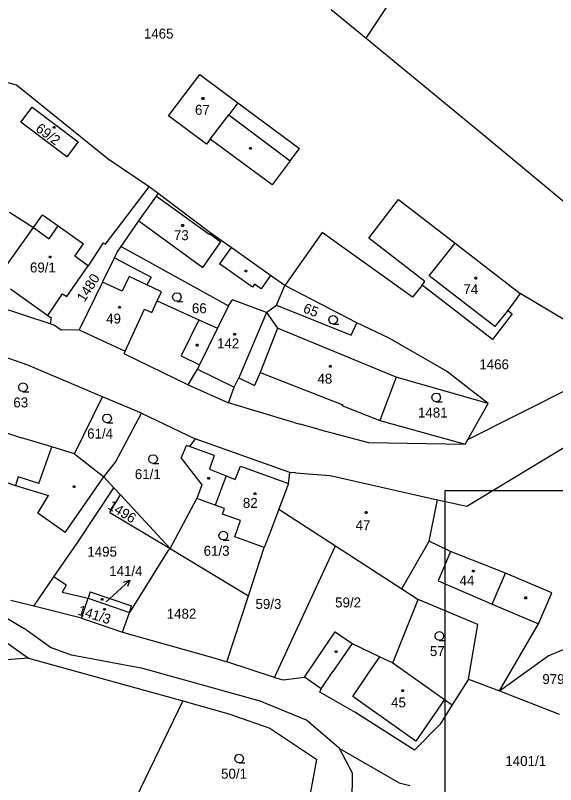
# Model space of a CAD drawing. Extents: x -852001 to -842497, y -1063614 to -1052182.
# Drawn here: x -849216.3 to -849124, y -1056255.4 to -1056124 of the extents above; entities that cross this region are included whole.
import ezdxf

# ---------------------------------------------------------------- set-up
doc = ezdxf.new("R2010")
doc.units = 0
for name, color, linetype in [('Default', 7, 'Continuous'), ('KN_HRANICE', 7, 'Continuous'), ('KN_KULTURY', 7, 'Continuous'), ('KN_PARCELY', 7, 'Continuous'), ('KN_SLUCKY', 7, 'Continuous'), ('LEGENDA', 7, 'Continuous')]:
    doc.layers.add(name, color=color, linetype=linetype)

# ---------------------------------------------------------------- blocks, each defined once
blk = doc.blocks.new('304')
at = {"layer": 'Default'}
blk.add_lwpolyline([(0, 0), (-0.38, 0.1), (-0.65, 0.37), (-0.75, 0.74), (-0.65, 1.11), (-0.38, 1.38), (-0.01, 1.48), (0.36, 1.38), (0.63, 1.11), (0.73, 0.73), (0.63, 0.35), (0.36, 0.08), (-0.02, -0.02), (0.98, -0.02)], dxfattribs=at)
blk = doc.blocks.new('NAHRADNI_SYMBOL')
at = {"layer": 'Default'}
blk.add_lwpolyline([(0.09, 0.15), (0.18, 0), (0.09, -0.15), (-0.09, -0.15), (-0.18, 0), (-0.09, 0.15), (0.09, 0.15)], dxfattribs=at)
blk = doc.blocks.new('10292')
at = {"layer": 'Default'}
blk.add_line((0, 3), (0, 0), dxfattribs=at)
blk.add_lwpolyline([(-0.5, 2), (0, 3), (0.5, 2)], dxfattribs=at)
blk = doc.blocks.new('402')
at = {"layer": 'Default'}
blk.add_lwpolyline([(0.09, 0.15), (0.18, 0), (0.09, -0.15), (-0.09, -0.15), (-0.18, 0), (-0.09, 0.15), (0.09, 0.15)], dxfattribs=at)

msp = doc.modelspace()

# ---------------------------------------------------------------- linework, layer by layer
at = {"layer": 'KN_HRANICE'}
for p, q in [((-849156.39, -1056127.95), (-849134.65, -1056094.95)), ((-849162.35, -1056123.05), (-849156.39, -1056127.95)), ((-849156.39, -1056127.95), (-849136.05, -1056144.68)), ((-849216.14, -1056135.95), (-849229.16, -1056132.38)), ((-849190.13, -1056141.21), (-849184.82, -1056134.14)), ((-849184.82, -1056134.14), (-849178.32, -1056138.97)), ((-849200.44, -1056148.6), (-849216.14, -1056135.95)), ((-849178.32, -1056138.97), (-849167.78, -1056146.8)), ((-849183.69, -1056146.04), (-849190.13, -1056141.21)), ((-849136.05, -1056144.68), (-849108.72, -1056167.41)), ((-849183.02, -1056145.16), (-849183.69, -1056146.04)), ((-849172.44, -1056152.99), (-849183.02, -1056145.16)), ((-849169.35, -1056148.89), (-849167.78, -1056146.8)), ((-849193.48, -1056153.3), (-849200.44, -1056148.6)), ((-849169.35, -1056148.89), (-849172.44, -1056152.99)), ((-849200.94, -1056163.12), (-849193.48, -1056153.3)), ((-849191.92, -1056154.48), (-849193.48, -1056153.3)), ((-849195.24, -1056159.11), (-849192.23, -1056154.91)), ((-849192.23, -1056154.91), (-849191.92, -1056154.48)), ((-849183.09, -1056161.13), (-849191.92, -1056154.48)), ((-849155.93, -1056162.08), (-849150.85, -1056155.51)), ((-849150.85, -1056155.51), (-849141.2, -1056162.97)), ((-849217.32, -1056157.67), (-849213.24, -1056160.29)), ((-849213.24, -1056160.29), (-849211.69, -1056158.1)), ((-849211.69, -1056158.1), (-849209, -1056160.01)), ((-849198.23, -1056163.51), (-849195.24, -1056159.11)), ((-849218.67, -1056167.97), (-849213.24, -1056160.29)), ((-849209, -1056160.01), (-849204.67, -1056163.07)), ((-849179.47, -1056163.69), (-849183.09, -1056161.13)), ((-849163.93, -1056161.11), (-849170.31, -1056170.18)), ((-849148.47, -1056172.18), (-849163.93, -1056161.11)), ((-849206.17, -1056165.19), (-849204.67, -1056163.07)), ((-849201.3, -1056162.87), (-849203.87, -1056166.8)), ((-849201.3, -1056162.87), (-849200.94, -1056163.12)), ((-849146.34, -1056169.48), (-849155.93, -1056162.08)), ((-849141.2, -1056162.97), (-849130.07, -1056171.57)), ((-849199.39, -1056165.45), (-849198.91, -1056164.5)), ((-849198.91, -1056164.5), (-849198.23, -1056163.51)), ((-849198.23, -1056163.51), (-849179.92, -1056173.67)), ((-849172.72, -1056168.47), (-849179.47, -1056163.69)), ((-849203.87, -1056166.8), (-849206.17, -1056165.19)), ((-849201.46, -1056169.6), (-849199.39, -1056165.45)), ((-849199.39, -1056165.45), (-849193.13, -1056168.74)), ((-849207.51, -1056172.06), (-849203.87, -1056166.8)), ((-849170.31, -1056170.18), (-849172.72, -1056168.47)), ((-849201.46, -1056169.6), (-849205.39, -1056177.77)), ((-849193.13, -1056168.74), (-849193.84, -1056170.06)), ((-849146.81, -1056170.1), (-849146.34, -1056169.48)), ((-849217.17, -1056170.75), (-849210.75, -1056175.28)), ((-849191.35, -1056171.24), (-849193.84, -1056170.06)), ((-849171.71, -1056173.55), (-849170.31, -1056170.18)), ((-849157.98, -1056176.57), (-849170.31, -1056170.18)), ((-849146.81, -1056170.1), (-849148.47, -1056172.18)), ((-849134.79, -1056179.4), (-849146.81, -1056170.1)), ((-849210.39, -1056176.75), (-849224.5, -1056172.08)), ((-849210.75, -1056175.28), (-849208.24, -1056171.61)), ((-849208.24, -1056171.61), (-849207.51, -1056172.06)), ((-849192.07, -1056172.77), (-849191.35, -1056171.24)), ((-849130.07, -1056171.57), (-849132.2, -1056174.42)), ((-849122.32, -1056176.18), (-849130.07, -1056171.57)), ((-849192.07, -1056172.77), (-849184.95, -1056176.04)), ((-849179.92, -1056173.67), (-849181.8, -1056177.49)), ((-849179.92, -1056173.67), (-849179.25, -1056172.62)), ((-849173.41, -1056174.79), (-849179.25, -1056172.62)), ((-849173.41, -1056174.79), (-849171.71, -1056173.55)), ((-849171.71, -1056173.55), (-849158.94, -1056178.64)), ((-849173.41, -1056174.79), (-849171.52, -1056177.46)), ((-849131.47, -1056175.04), (-849134.79, -1056179.4)), ((-849132.2, -1056174.42), (-849131.47, -1056175.04)), ((-849210.75, -1056175.28), (-849210.2, -1056175.67)), ((-849210.2, -1056175.67), (-849210.39, -1056176.75)), ((-849184.95, -1056176.04), (-849181.8, -1056177.49)), ((-849209.65, -1056177), (-849210.39, -1056176.75)), ((-849208.48, -1056177.82), (-849209.65, -1056177)), ((-849181.8, -1056177.49), (-849184.87, -1056183.74)), ((-849171.52, -1056177.46), (-849174.47, -1056185.05)), ((-849158.94, -1056178.64), (-849157.98, -1056176.57)), ((-849152.47, -1056179.17), (-849157.98, -1056176.57)), ((-849205.39, -1056177.77), (-849208.48, -1056177.82)), ((-849205.39, -1056177.77), (-849197.58, -1056181.42)), ((-849142.67, -1056184.79), (-849152.47, -1056179.17)), ((-849197.58, -1056181.42), (-849197.79, -1056181.8)), ((-849214.19, -1056183.77), (-849219.9, -1056181.81)), ((-849197.79, -1056181.8), (-849186.8, -1056187.14)), ((-849139, -1056196.47), (-849111.09, -1056182.39)), ((-849201.43, -1056189.17), (-849214.19, -1056183.77)), ((-849184.87, -1056183.74), (-849185.22, -1056184.46)), ((-849186.8, -1056187.14), (-849185.22, -1056184.46)), ((-849174.47, -1056185.05), (-849175.47, -1056187.27)), ((-849135.54, -1056190.32), (-849142.67, -1056184.79)), ((-849178.93, -1056187.55), (-849178.15, -1056185.97)), ((-849178.15, -1056185.97), (-849175.47, -1056187.27)), ((-849151.28, -1056185.84), (-849154.04, -1056193.23)), ((-849135.54, -1056190.32), (-849151.28, -1056185.84)), ((-849186.8, -1056187.14), (-849179.92, -1056190.19)), ((-849179.92, -1056190.19), (-849178.93, -1056187.55)), ((-849206.24, -1056198.9), (-849201.43, -1056189.17)), ((-849194.76, -1056191.99), (-849201.43, -1056189.17)), ((-849139.2, -1056207.88), (-849107.15, -1056188.47)), ((-849169.32, -1056193.41), (-849179.92, -1056190.19)), ((-849139, -1056196.47), (-849135.54, -1056190.32)), ((-849199.24, -1056200.34), (-849194.76, -1056191.99)), ((-849194.76, -1056191.99), (-849185.6, -1056196.38)), ((-849168.67, -1056193.56), (-849169.32, -1056193.41)), ((-849154.04, -1056193.23), (-849139.45, -1056197.27)), ((-849219.79, -1056194.73), (-849215.25, -1056196.17)), ((-849168.67, -1056193.56), (-849167.69, -1056193.85)), ((-849164.4, -1056194.78), (-849167.69, -1056193.85)), ((-849164.4, -1056194.78), (-849156.01, -1056196.98)), ((-849210.06, -1056197.72), (-849215.25, -1056196.17)), ((-849185.6, -1056196.38), (-849186.57, -1056197.69)), ((-849169.42, -1056202.11), (-849185.6, -1056196.38)), ((-849156.01, -1056196.98), (-849139.45, -1056197.27)), ((-849139.45, -1056197.27), (-849139, -1056196.47)), ((-849206.24, -1056198.9), (-849210.06, -1056197.72)), ((-849188.02, -1056199.66), (-849187.1, -1056197.5)), ((-849186.57, -1056197.69), (-849187.1, -1056197.5)), ((-849206.24, -1056198.9), (-849201.22, -1056202.84)), ((-849188.02, -1056199.66), (-849184.45, -1056204.23)), ((-849201.22, -1056202.84), (-849199.24, -1056200.34)), ((-849169.66, -1056204.02), (-849169.42, -1056202.11)), ((-849168.44, -1056202.2), (-849169.42, -1056202.11)), ((-849168.44, -1056202.2), (-849162.53, -1056202.65)), ((-849162.53, -1056202.65), (-849144.18, -1056206.76)), ((-849201.22, -1056202.84), (-849199.47, -1056204.74)), ((-849205.78, -1056214.2), (-849199.47, -1056204.74)), ((-849199.47, -1056204.74), (-849198.37, -1056205.93)), ((-849184.45, -1056204.23), (-849185.31, -1056206.53)), ((-849169.66, -1056204.02), (-849171.3, -1056208.37)), ((-849200.16, -1056208.92), (-849198.37, -1056205.93)), ((-849198.37, -1056205.93), (-849189.89, -1056215.12)), ((-849189.89, -1056215.12), (-849185.31, -1056206.53)), ((-849182.16, -1056207.7), (-849185.31, -1056206.53)), ((-849180.61, -1056208.28), (-849182.16, -1056207.7)), ((-849145.61, -1056213.86), (-849144.18, -1056206.76)), ((-849144.18, -1056206.76), (-849139.2, -1056207.88)), ((-849200.16, -1056208.92), (-849189.89, -1056215.12)), ((-849180.96, -1056209.23), (-849180.61, -1056208.28)), ((-849177.84, -1056210.33), (-849180.96, -1056209.23)), ((-849171.3, -1056208.37), (-849172.75, -1056212.2)), ((-849171.3, -1056208.37), (-849161.61, -1056214.65)), ((-849178.84, -1056213.13), (-849177.84, -1056210.33)), ((-849173.81, -1056214.95), (-849178.84, -1056213.13)), ((-849172.75, -1056212.2), (-849173.81, -1056214.95)), ((-849209.73, -1056219.93), (-849205.78, -1056214.2)), ((-849150.29, -1056221.98), (-849145.61, -1056213.86)), ((-849141.96, -1056215.62), (-849145.61, -1056213.86)), ((-849190.25, -1056215.51), (-849196.84, -1056226)), ((-849189.89, -1056215.12), (-849190.25, -1056215.51)), ((-849189.89, -1056215.12), (-849176.5, -1056223.2)), ((-849176.5, -1056223.2), (-849173.81, -1056214.95)), ((-849172.06, -1056237.11), (-849161.61, -1056214.65)), ((-849161.61, -1056214.65), (-849150.29, -1056221.98)), ((-849132.6, -1056219.32), (-849141.96, -1056215.62)), ((-849124.65, -1056222.67), (-849132.6, -1056219.32)), ((-849213.19, -1056224.95), (-849209.73, -1056219.93)), ((-849207.63, -1056221.36), (-849209.73, -1056219.93)), ((-849225.53, -1056222.34), (-849214.82, -1056228.77)), ((-849207.63, -1056221.36), (-849208.34, -1056222.56)), ((-849150.29, -1056221.98), (-849147.5, -1056223.79)), ((-849208.34, -1056222.56), (-849203.88, -1056223.57)), ((-849203.52, -1056222.51), (-849203.88, -1056223.57)), ((-849203.88, -1056223.57), (-849196.84, -1056226)), ((-849203.52, -1056222.51), (-849196.47, -1056224.89)), ((-849180.18, -1056234.46), (-849176.5, -1056223.2)), ((-849126.97, -1056227.99), (-849124.65, -1056222.67)), ((-849213.19, -1056224.95), (-849217.08, -1056223.98)), ((-849205.03, -1056227), (-849213.19, -1056224.95)), ((-849196.84, -1056226), (-849196.47, -1056224.89)), ((-849151.82, -1056234.65), (-849147.5, -1056223.79)), ((-849137.29, -1056228.1), (-849147.5, -1056223.79)), ((-849197.99, -1056229.41), (-849196.84, -1056226)), ((-849205.03, -1056227), (-849197.99, -1056229.41)), ((-849210.34, -1056232), (-849214.82, -1056228.77)), ((-849138.93, -1056237.39), (-849137.29, -1056228.1)), ((-849133.63, -1056239.4), (-849126.97, -1056227.99)), ((-849197.99, -1056229.41), (-849182.44, -1056233.76)), ((-849164.95, -1056234.13), (-849161.69, -1056229.33)), ((-849161.69, -1056229.33), (-849158.8, -1056231.3)), ((-849125.31, -1056233.41), (-849117.03, -1056230)), ((-849218.47, -1056230.72), (-849214.07, -1056233.83)), ((-849158.8, -1056231.3), (-849154.03, -1056233.59)), ((-849206.7, -1056233.3), (-849210.34, -1056232)), ((-849214.07, -1056233.83), (-849233.7, -1056235.39)), ((-849214.07, -1056233.83), (-849187.73, -1056241.12)), ((-849194.53, -1056235.61), (-849206.7, -1056233.3)), ((-849182.44, -1056233.76), (-849180.18, -1056234.46)), ((-849166.94, -1056237.05), (-849164.95, -1056234.13)), ((-849154.03, -1056233.59), (-849151.82, -1056234.65)), ((-849133.63, -1056239.4), (-849125.31, -1056233.41)), ((-849172.06, -1056237.11), (-849180.18, -1056234.46)), ((-849151.82, -1056234.65), (-849143.03, -1056240.87)), ((-849174.51, -1056241.18), (-849194.53, -1056235.61)), ((-849172.06, -1056237.11), (-849170.59, -1056237.53)), ((-849170.59, -1056237.53), (-849166.94, -1056237.05)), ((-849164.05, -1056239.04), (-849166.94, -1056237.05)), ((-849138.93, -1056237.39), (-849141.7, -1056241.81)), ((-849138.93, -1056237.39), (-849133.63, -1056239.4)), ((-849164.31, -1056239.64), (-849164.05, -1056239.04)), ((-849133.63, -1056239.4), (-849123.4, -1056243.38)), ((-849158.31, -1056243.07), (-849164.31, -1056239.64)), ((-849187.73, -1056241.12), (-849195.81, -1056257.87)), ((-849187.73, -1056241.12), (-849179.87, -1056243.33)), ((-849166.56, -1056244.39), (-849174.51, -1056241.18)), ((-849141.7, -1056241.81), (-849143.76, -1056245.1)), ((-849143.03, -1056240.87), (-849141.7, -1056241.81)), ((-849179.87, -1056243.33), (-849172.85, -1056245.8)), ((-849148.13, -1056249.54), (-849158.31, -1056243.07)), ((-849160.92, -1056249.26), (-849166.56, -1056244.39)), ((-849172.85, -1056245.8), (-849164.8, -1056251.16)), ((-849143.76, -1056245.1), (-849148.13, -1056249.54)), ((-849158.72, -1056253.46), (-849160.92, -1056249.26)), ((-849160.92, -1056249.26), (-849150.75, -1056255.14)), ((-849166.92, -1056262.43), (-849164.8, -1056251.16)), ((-849158.79, -1056259.59), (-849158.72, -1056253.46)), ((-849150.75, -1056255.14), (-849148.92, -1056255.56))]:
    msp.add_line(p, q, dxfattribs=at)
at = {"layer": 'KN_PARCELY'}
msp.add_line((-849200.78, -1056224.19), (-849198.99, -1056222.55), dxfattribs=at)
at = {"layer": 'KN_SLUCKY'}
for p, q in [((-849178.32, -1056138.97), (-849179.84, -1056141.02)), ((-849215.38, -1056142.29), (-849213.42, -1056139.7)), ((-849213.42, -1056139.7), (-849205.59, -1056145.62)), ((-849183.02, -1056145.16), (-849179.84, -1056141.02)), ((-849179.84, -1056141.02), (-849169.35, -1056148.89)), ((-849207.55, -1056148.21), (-849215.38, -1056142.29)), ((-849205.59, -1056145.62), (-849207.55, -1056148.21)), ((-849192.23, -1056154.91), (-849183.2, -1056161.41)), ((-849195.24, -1056159.11), (-849184.29, -1056167.12)), ((-849213.24, -1056160.29), (-849210.54, -1056162.19)), ((-849210.54, -1056162.19), (-849209, -1056160.01)), ((-849183.2, -1056161.41), (-849183.11, -1056161.33)), ((-849183.11, -1056161.33), (-849181.19, -1056162.7)), ((-849184.29, -1056167.12), (-849181.19, -1056162.7)), ((-849145.62, -1056168.53), (-849141.2, -1056162.97)), ((-849179.47, -1056163.69), (-849181.44, -1056166.48)), ((-849175.83, -1056170.45), (-849181.44, -1056166.48)), ((-849172.72, -1056168.47), (-849174.31, -1056170.73)), ((-849134.39, -1056177.2), (-849145.62, -1056168.53)), ((-849198.06, -1056171.16), (-849201.46, -1056169.6)), ((-849196.86, -1056168.63), (-849198.06, -1056171.16)), ((-849193.84, -1056170.06), (-849196.86, -1056168.63)), ((-849175.46, -1056169.92), (-849175.83, -1056170.45)), ((-849174.31, -1056170.73), (-849175.46, -1056169.92)), ((-849193.01, -1056174.76), (-849192.07, -1056172.77)), ((-849197.58, -1056181.42), (-849194.23, -1056174.19)), ((-849194.23, -1056174.19), (-849193.01, -1056174.76)), ((-849173.41, -1056174.79), (-849178.15, -1056185.97)), ((-849132.2, -1056174.42), (-849134.39, -1056177.2)), ((-849184.95, -1056176.04), (-849187.98, -1056182.21)), ((-849151.28, -1056185.84), (-849171.52, -1056177.46)), ((-849187.98, -1056182.21), (-849184.87, -1056183.74)), ((-849185.22, -1056184.46), (-849178.93, -1056187.55)), ((-849174.47, -1056185.05), (-849160.38, -1056190.53)), ((-849160.38, -1056190.53), (-849160.53, -1056190.66)), ((-849160.53, -1056190.66), (-849154.04, -1056193.23)), ((-849212.29, -1056203.97), (-849210.06, -1056197.72)), ((-849182.36, -1056199.24), (-849186.57, -1056197.69)), ((-849182.36, -1056199.24), (-849183.16, -1056201.52)), ((-849178.76, -1056203.33), (-849177.88, -1056201.01)), ((-849177.88, -1056201.01), (-849169.66, -1056204.02)), ((-849183.16, -1056201.52), (-849180.29, -1056202.7)), ((-849180.29, -1056202.7), (-849182.16, -1056207.7)), ((-849180.29, -1056202.7), (-849178.76, -1056203.33)), ((-849217.77, -1056203.84), (-849216.27, -1056204.31)), ((-849215.83, -1056202.87), (-849216.27, -1056204.31)), ((-849212.29, -1056203.97), (-849215.83, -1056202.87)), ((-849207.8, -1056212.38), (-849201.22, -1056202.84)), ((-849216.27, -1056204.31), (-849210.64, -1056206.06)), ((-849212.49, -1056209.07), (-849210.64, -1056206.06)), ((-849207.8, -1056212.38), (-849212.49, -1056209.07)), ((-849141.96, -1056215.62), (-849144.08, -1056220.62)), ((-849134.87, -1056224.59), (-849132.6, -1056219.32)), ((-849144.08, -1056220.62), (-849134.87, -1056224.59)), ((-849205.03, -1056227), (-849203.88, -1056223.57)), ((-849134.87, -1056224.59), (-849126.97, -1056227.99)), ((-849158.8, -1056231.3), (-849162.06, -1056236.09)), ((-849155.97, -1056236.4), (-849154.03, -1056233.59)), ((-849164.05, -1056239.04), (-849162.06, -1056236.09)), ((-849158.69, -1056240.35), (-849155.97, -1056236.4)), ((-849147.9, -1056247.99), (-849158.69, -1056240.35)), ((-849143.03, -1056240.87), (-849147.9, -1056247.99))]:
    msp.add_line(p, q, dxfattribs=at)
at = {"layer": 'LEGENDA'}
msp.add_lwpolyline([(-849142.95, -1056625.24), (-848548.95, -1056625.24), (-848548.95, -1056205.24), (-849142.95, -1056205.24)], close=True, dxfattribs=at)

# ---------------------------------------------------------------- block references
at = {"layer": 'KN_KULTURY'}
for name, p in [('402', (-849184.27, -1056138.24)), ('402', (-849209.7, -1056143.15)), ('402', (-849176.16, -1056146.73)), ('402', (-849187.74, -1056159.93)), ('402', (-849210.38, -1056165.31)), ('402', (-849176.95, -1056167.68)), ('402', (-849137.67, -1056168.92)), ('304', (-849188.72, -1056172.88)), ('402', (-849198.52, -1056173.91)), ('304', (-849162.03, -1056176.77)), ('402', (-849178.86, -1056178.52)), ('402', (-849185.25, -1056180.37)), ('402', (-849162.52, -1056183.98)), ('304', (-849215, -1056188.3)), ('304', (-849144.41, -1056190.03)), ('304', (-849200.65, -1056193.61)), ('304', (-849192.79, -1056200.55)), ('402', (-849183.29, -1056203.12)), ('402', (-849206.29, -1056204.53)), ('402', (-849175.38, -1056205.72)), ('NAHRADNI_SYMBOL', (-849156.39, -1056208.95)), ('304', (-849180.79, -1056213.64)), ('402', (-849138.08, -1056218.92)), ('402', (-849201.5, -1056223.77)), ('402', (-849129.14, -1056223.52)), ('402', (-849201.08, -1056225.48)), ('304', (-849143.88, -1056230.77)), ('402', (-849161.53, -1056232.73)), ('402', (-849150.15, -1056239.38)), ('304', (-849178.09, -1056251.71))]:
    msp.add_blockref(name, p, dxfattribs=at)
at = {"layer": 'KN_PARCELY', "rotation": -47.62341000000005}
msp.add_blockref('10292', (-849198.99, -1056222.55), dxfattribs=at)

# ---------------------------------------------------------------- texts
at = {"layer": 'KN_PARCELY'}
for s, height, p in [('1465', 1.7, (-849194.36, -1056128)), ('67', 1.7, (-849185.63, -1056141.02)), ('73', 1.7, (-849189.23, -1056162.43)), ('69/1', 1.7, (-849213.82, -1056167.95)), ('74', 1.7, (-849139.77, -1056171.65)), ('66', 1.7, (-849186.16, -1056174.91)), ('49', 1.7, (-849200.81, -1056176.67)), ('142', 1.7, (-849181.87, -1056180.91)), ('1466', 1.7, (-849137.06, -1056184.49)), ('48', 1.7, (-849164.71, -1056186.94)), ('63', 1.7, (-849216.66, -1056191)), ('1481', 1.7, (-849147.53, -1056192.73)), ('61/4', 1.7, (-849204.05, -1056196.31)), ('61/1', 1.7, (-849195.91, -1056203.25)), ('82', 1.7, (-849177.45, -1056208.16)), ('47', 1.7, (-849158.2, -1056211.98)), ('1495', 1.7, (-849204.02, -1056216.48)), ('61/3', 1.7, (-849184.15, -1056216.34)), ('141/4', 1.7, (-849200.29, -1056219.8)), ('44', 1.7, (-849140.44, -1056221.41)), ('59/3', 1.7, (-849175.3, -1056225.41)), ('59/2', 1.7, (-849161.69, -1056225.16)), ('141/4', 0.1, (-849201.03, -1056224.19)), ('1482', 1.7, (-849190.46, -1056227.09)), ('57', 1.7, (-849145.5, -1056233.47)), ('979/9', 1.7, (-849126.29, -1056238.25)), ('45', 1.7, (-849152.13, -1056242.24)), ('1401/1', 1.7, (-849132.61, -1056252.24)), ('50/1', 1.7, (-849181.17, -1056254.41))]:
    msp.add_text(s, height=height, dxfattribs=at).set_placement(p)
for s, rotation, p in [('69/2', 323.492, (-849213, -1056143.69)), ('1480', 57.582, (-849204.52, -1056173.14)), ('65', 337.931, (-849167.3, -1056174.69)), ('1496', 328.305, (-849200.68, -1056208.2)), ('141/3', 342.743, (-849205.78, -1056226.37))]:
    msp.add_text(s, height=1.7, rotation=rotation, dxfattribs=at).set_placement(p)

doc.saveas('drawing.dxf')
